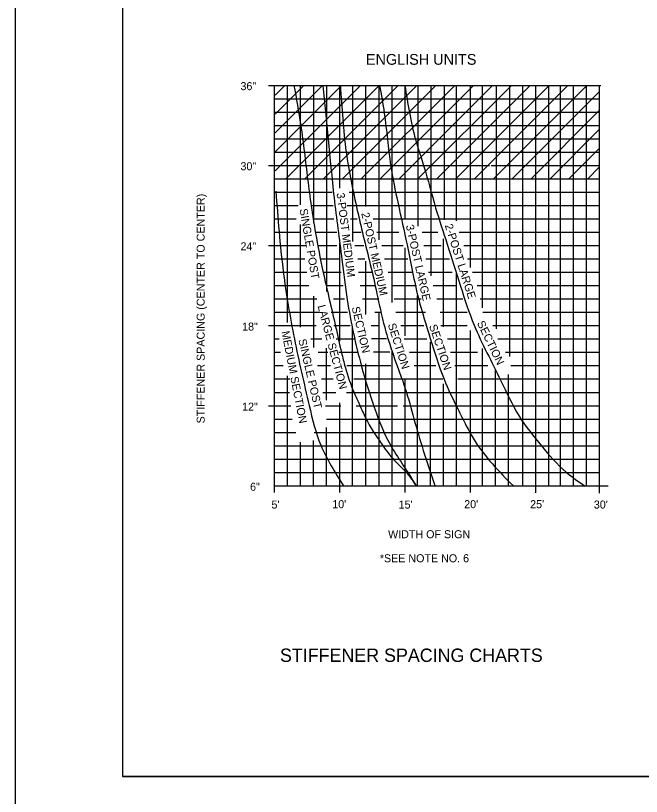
# Model space of a CAD drawing. Extents: x 650495 to 651400, y 297864 to 299646.
# Drawn here: x 650495.3 to 650729.8, y 299059.1 to 299351.6 of the extents above; entities that cross this region are included whole.
import ezdxf

# ---------------------------------------------------------------- set-up
doc = ezdxf.new("R2010")
doc.units = 0
for name, color, linetype in [('1', 7, 'Continuous'), ('2', 7, 'Continuous'), ('3', 7, 'Continuous'), ('PLT-BNDY', 7, 'Continuous')]:
    doc.layers.add(name, color=color, linetype=linetype)

msp = doc.modelspace()

# ---------------------------------------------------------------- linework, layer by layer
at = {"layer": '1'}
for p, q in [((650535.31, 299630.63), (650535.31, 299066.63)), ((651321.31, 299066.63), (650535.31, 299066.63)), ((650535.31, 299066.63), (651121.31, 299066.63))]:
    msp.add_line(p, q, dxfattribs=at)
at = {"layer": '2'}
for p, q in [((650590.03, 299325.48), (650714.65, 299325.48)), ((650592.53, 299321.8), (650596.21, 299325.48)), ((650592.53, 299314.72), (650603.28, 299325.48)), ((650592.53, 299307.65), (650610.36, 299325.48)), ((650592.53, 299300.58), (650617.43, 299325.48)), ((650592.53, 299293.51), (650624.5, 299325.48)), ((650595.28, 299325.48), (650595.28, 299325.48)), ((650596.57, 299290.48), (650631.57, 299325.48)), ((650603.64, 299290.48), (650638.64, 299325.48)), ((650607.53, 299325.48), (650607.53, 299325.48)), ((650610.71, 299290.48), (650645.71, 299325.48)), ((650617.78, 299290.48), (650652.78, 299325.48)), ((650624.85, 299290.48), (650659.85, 299325.48)), ((650625.9, 299325.48), (650625.9, 299325.48)), ((650631.28, 299325.48), (650631.28, 299325.48)), ((650631.92, 299290.48), (650666.92, 299325.48)), ((650639, 299290.48), (650674, 299325.48)), ((650646.07, 299290.48), (650681.07, 299325.48)), ((650653.14, 299290.48), (650688.14, 299325.48)), ((650660.21, 299290.48), (650695.21, 299325.48)), ((650661.15, 299325.48), (650661.15, 299325.48)), ((650667.28, 299290.48), (650702.28, 299325.48)), ((650674.35, 299290.48), (650709.35, 299325.48)), ((650681.42, 299290.48), (650714.03, 299323.09)), ((650592.53, 299320.48), (650714.03, 299320.48)), ((650607.53, 299320.48), (650607.53, 299320.48)), ((650632.53, 299317.86), (650632.53, 299317.86)), ((650688.49, 299290.48), (650714.03, 299316.02)), ((650592.53, 299315.48), (650714.03, 299315.48)), ((650592.53, 299310.48), (650714.03, 299310.48)), ((650633.65, 299310.48), (650633.65, 299310.48)), ((650695.56, 299290.48), (650714.03, 299308.95)), ((650592.53, 299305.48), (650714.03, 299305.48)), ((650627.53, 299305.48), (650627.53, 299305.48)), ((650665.15, 299305.48), (650665.15, 299305.48)), ((650702.63, 299290.48), (650714.03, 299301.87)), ((650592.53, 299300.48), (650714.03, 299300.48)), ((650590.03, 299295.48), (650672.9, 299295.48)), ((650597.53, 299295.48), (650597.53, 299295.48)), ((650636.78, 299295.48), (650636.78, 299295.48)), ((650673.53, 299295.48), (650714.03, 299295.48)), ((650709.71, 299290.48), (650714.03, 299294.8)), ((650592.53, 299290.48), (650714.03, 299290.48)), ((650609.9, 299290.48), (650609.9, 299290.48)), ((650592.53, 299285.48), (650613.94, 299285.48)), ((650620.28, 299285.48), (650714.03, 299285.48)), ((650592.53, 299280.48), (650601.15, 299280.48)), ((650605.9, 299280.48), (650614.33, 299280.48)), ((650619.59, 299280.48), (650714.03, 299280.48)), ((650592.53, 299275.48), (650600.46, 299275.48)), ((650606.9, 299275.48), (650614.53, 299275.48)), ((650612.53, 299275.48), (650612.53, 299275.48)), ((650620.77, 299275.48), (650623.35, 299275.48)), ((650629.3, 299275.48), (650714.03, 299275.48)), ((650592.53, 299270.48), (650601.85, 299270.48)), ((650607.78, 299270.48), (650615.72, 299270.48)), ((650621.67, 299270.48), (650624.74, 299270.48)), ((650630.68, 299270.48), (650638.9, 299270.48)), ((650647.62, 299270.48), (650653.57, 299270.48)), ((650661.5, 299270.48), (650714.03, 299270.48)), ((650590.03, 299265.48), (650604.15, 299265.48)), ((650608.78, 299265.48), (650615.62, 299265.48)), ((650622.36, 299265.48), (650625.73, 299265.48)), ((650632.57, 299265.48), (650640.53, 299265.48)), ((650648.22, 299265.48), (650654.76, 299265.48)), ((650663.28, 299265.48), (650714.03, 299265.48)), ((650592.53, 299260.48), (650603.63, 299260.48)), ((650609.65, 299260.48), (650616.65, 299260.48)), ((650623.55, 299260.48), (650626.22, 299260.48)), ((650633.56, 299260.48), (650642.28, 299260.48)), ((650647.53, 299260.48), (650647.53, 299260.48)), ((650649.01, 299260.48), (650657.93, 299260.48)), ((650664.67, 299260.48), (650714.03, 299260.48)), ((650592.53, 299255.48), (650604.43, 299255.48)), ((650610.65, 299255.48), (650617.31, 299255.48)), ((650623.85, 299255.48), (650628.8, 299255.48)), ((650634.94, 299255.48), (650643.9, 299255.48)), ((650650, 299255.48), (650658.92, 299255.48)), ((650666.45, 299255.48), (650714.03, 299255.48)), ((650592.53, 299250.48), (650605.22, 299250.48)), ((650611.65, 299250.48), (650618.1, 299250.48)), ((650624.44, 299250.48), (650629.99, 299250.48)), ((650636.13, 299250.48), (650645.53, 299250.48)), ((650651.79, 299250.48), (650660.31, 299250.48)), ((650668.23, 299250.48), (650714.03, 299250.48)), ((650592.53, 299245.48), (650608.15, 299245.48)), ((650614.43, 299245.48), (650618.6, 299245.48)), ((650625.23, 299245.48), (650631.38, 299245.48)), ((650637.12, 299245.48), (650647.28, 299245.48)), ((650653.17, 299245.48), (650662.88, 299245.48)), ((650669.42, 299245.48), (650714.03, 299245.48)), ((650592.53, 299240.48), (650609.15, 299240.48)), ((650607.53, 299240.48), (650607.53, 299240.48)), ((650613.53, 299240.48), (650619.69, 299240.48)), ((650629.9, 299240.48), (650632.37, 299240.48)), ((650637.72, 299240.48), (650648.9, 299240.48)), ((650654.36, 299240.48), (650664.47, 299240.48)), ((650670.41, 299240.48), (650714.03, 299240.48)), ((650590.03, 299235.48), (650607.9, 299235.48)), ((650592.53, 299235.48), (650592.53, 299235.48)), ((650614.53, 299235.48), (650620.68, 299235.48)), ((650628.6, 299235.48), (650631.18, 299235.48)), ((650639.7, 299235.48), (650648.22, 299235.48)), ((650648.78, 299235.48), (650648.78, 299235.48)), ((650654.65, 299235.48), (650664.47, 299235.48)), ((650674.18, 299235.48), (650714.03, 299235.48)), ((650592.53, 299230.48), (650594.12, 299230.48)), ((650605.91, 299230.48), (650610.07, 299230.48)), ((650615.4, 299230.48), (650622.36, 299230.48)), ((650634.25, 299230.48), (650628.7, 299230.48)), ((650640.89, 299230.48), (650649.41, 299230.48)), ((650657.14, 299230.48), (650665.85, 299230.48)), ((650675.96, 299230.48), (650714.03, 299230.48)), ((650592.53, 299225.48), (650594.52, 299225.48)), ((650608.69, 299225.48), (650612.28, 299225.48)), ((650616.4, 299225.48), (650623.75, 299225.48)), ((650635.54, 299225.48), (650629.39, 299225.48)), ((650642.87, 299225.48), (650650.6, 299225.48)), ((650658.32, 299225.48), (650668.43, 299225.48)), ((650678.93, 299225.48), (650714.03, 299225.48)), ((650592.53, 299220.48), (650595.51, 299220.48)), ((650608.49, 299220.48), (650613.28, 299220.48)), ((650619.39, 299220.48), (650635.93, 299220.48)), ((650644.65, 299220.48), (650652.78, 299220.48)), ((650659.91, 299220.48), (650672.2, 299220.48)), ((650680.91, 299220.48), (650714.03, 299220.48)), ((650708.9, 299220.48), (650708.9, 299220.48)), ((650592.53, 299215.48), (650598.03, 299215.48)), ((650609.88, 299215.48), (650614.28, 299215.48)), ((650612.53, 299215.48), (650612.53, 299215.48)), ((650622.06, 299215.48), (650655.45, 299215.48)), ((650659.9, 299215.48), (650659.9, 299215.48)), ((650661, 299215.48), (650714.03, 299215.48)), ((650592.53, 299210.48), (650597.99, 299210.48)), ((650610.47, 299210.48), (650615.28, 299210.48)), ((650619.28, 299210.48), (650714.03, 299210.48)), ((650590.03, 299205.48), (650598.48, 299205.48)), ((650597.53, 299205.48), (650597.53, 299205.48)), ((650611.46, 299205.48), (650617.21, 299205.48)), ((650622.95, 299205.48), (650638.4, 299205.48)), ((650640.53, 299205.48), (650714.03, 299205.48)), ((650592.53, 299200.48), (650598.98, 299200.48)), ((650611.86, 299200.48), (650714.03, 299200.48)), ((650592.53, 299195.48), (650600.27, 299195.48)), ((650607.15, 299195.48), (650714.03, 299195.48)), ((650642.53, 299195.48), (650642.53, 299195.48)), ((650686.78, 299195.48), (650686.78, 299195.48)), ((650592.53, 299190.48), (650714.03, 299190.48)), ((650692.53, 299190.48), (650692.53, 299190.48)), ((650592.53, 299185.48), (650714.03, 299185.48)), ((650627.53, 299185.48), (650627.53, 299185.48)), ((650650.15, 299185.48), (650650.15, 299185.48)), ((650687.53, 299185.48), (650687.53, 299185.48)), ((650699.9, 299185.48), (650699.9, 299185.48)), ((650592.53, 299180.48), (650714.03, 299180.48)), ((650607.53, 299180.48), (650607.53, 299180.48)), ((650592.15, 299175.48), (650717.28, 299175.48)), ((650712.53, 299175.48), (650712.53, 299175.48))]:
    msp.add_line(p, q, dxfattribs=at)
for points in [[(650592.15, 299325.48), (650592.15, 299172.98)], [(650597.03, 299325.48), (650597.03, 299236.61)], [(650601.9, 299325.48), (650601.9, 299280.74)], [(650606.9, 299325.48), (650606.9, 299273.98)], [(650611.78, 299325.48), (650611.78, 299248.23)], [(650616.65, 299325.48), (650616.65, 299286.98)], [(650621.53, 299325.48), (650621.53, 299266.96)], [(650626.4, 299325.48), (650626.4, 299280.04)], [(650631.4, 299325.48), (650631.4, 299267.56)], [(650636.28, 299325.48), (650636.28, 299244.17)], [(650641.15, 299325.48), (650641.15, 299275.36)], [(650646.03, 299325.48), (650646.03, 299272.71)], [(650650.9, 299325.48), (650650.9, 299254.08)], [(650655.9, 299325.48), (650655.9, 299275.09)], [(650660.4, 299325.48), (650660.4, 299274.69)], [(650665.65, 299325.48), (650665.65, 299257.25)], [(650670.15, 299325.48), (650670.15, 299242.19)], [(650675.4, 299325.48), (650675.4, 299234.26)], [(650680.4, 299325.48), (650680.4, 299223.95)], [(650685.28, 299325.48), (650685.28, 299175.48)], [(650690.15, 299325.48), (650690.15, 299172.81)], [(650695.03, 299325.48), (650695.03, 299175.48)], [(650699.4, 299325.48), (650699.4, 299175.48)], [(650704.28, 299325.48), (650704.28, 299175.48)], [(650709.15, 299325.48), (650709.15, 299175.48)], [(650714.03, 299325.48), (650714.03, 299172.77)], [(650601.9, 299273.4), (650601.9, 299234.86)], [(650616.65, 299266.47), (650616.65, 299229.6)], [(650655.53, 299267.95), (650655.53, 299235.05)], [(650641.15, 299264.61), (650641.15, 299231.68)], [(650626.4, 299259.63), (650626.4, 299239.61)], [(650660.4, 299255.47), (650660.4, 299175.48)], [(650606.9, 299246.45), (650606.9, 299227.22)], [(650645.78, 299246.75), (650645.78, 299175.48)], [(650631.4, 299240.6), (650631.4, 299175.48)], [(650621.4, 299235.05), (650621.4, 299175.48)], [(650665.65, 299233.66), (650665.65, 299172.98)], [(650650.65, 299229.3), (650650.65, 299175.48)], [(650611.65, 299226.98), (650611.65, 299207.6)], [(650636.28, 299225.93), (650636.28, 299175.48)], [(650670.15, 299226.93), (650670.15, 299175.48)], [(650626.4, 299221.18), (650626.4, 299175.48)], [(650597.03, 299216.72), (650597.03, 299175.48)], [(650675.03, 299219), (650675.03, 299175.48)], [(650679.9, 299217.21), (650679.9, 299175.48)], [(650641.15, 299215.63), (650641.15, 299172.98)], [(650655.53, 299213.65), (650655.53, 299175.48)], [(650616.65, 299206.61), (650616.65, 299172.98)], [(650611.65, 299197.29), (650611.65, 299175.48)], [(650601.9, 299191.84), (650601.9, 299175.48)], [(650606.78, 299192.44), (650606.78, 299175.48)]]:
    msp.add_lwpolyline(points, dxfattribs=at)
for points in [[(650599.57, 299325.48), (650602.15, 299310.57), (650604.72, 299290.35), (650607.7, 299270.13), (650610.47, 299255.86), (650612.85, 299245.36), (650615.23, 299235.05), (650617.41, 299225.34), (650618.79, 299219.99), (650622.16, 299210.28), (650624.14, 299205.92), (650626.52, 299200.76), (650629.3, 299195.81), (650632.27, 299191.45), (650636.63, 299185.7), (650641.98, 299180.15), (650645.35, 299175.48)], [(650610.47, 299325.48), (650612.45, 299305.41), (650614.63, 299283.41), (650617.6, 299260.22), (650619.59, 299245.16), (650624.94, 299220.19), (650629.69, 299204.93), (650636.23, 299189.86), (650640.59, 299183.12), (650645.35, 299175.48)], [(650617.01, 299325.48), (650619.19, 299300.48), (650623.35, 299278.66), (650624.94, 299271.72), (650630.09, 299250.31), (650632.66, 299238.52), (650635.04, 299229.9), (650638.81, 299219), (650641.78, 299210.48), (650644.95, 299199.18), (650652.48, 299175.2)], [(650631.67, 299325.48), (650633.46, 299315.12), (650635.83, 299295.5), (650638.61, 299281.23), (650641.98, 299265.77), (650646.34, 299245.36), (650650.7, 299230.69), (650655.85, 299215.43), (650661, 299204.33), (650664.17, 299197.99), (650667.14, 299192.64), (650681.81, 299175.48)], [(650641.18, 299325.48), (650645.15, 299305.22), (650648.32, 299295.11), (650652.68, 299279.65), (650657.04, 299265.97), (650661.99, 299250.31), (650667.14, 299235.65), (650677.05, 299215.03), (650683.99, 299201.56), (650692.31, 299190.46), (650701.62, 299180.55), (650708.75, 299175.39)], [(650592.84, 299285.79), (650595.61, 299255.66), (650599.77, 299230.49), (650605.32, 299205.52), (650609.68, 299190.66), (650618.2, 299175.48)]]:
    msp.add_spline(points, degree=3, dxfattribs=at)
at = {"layer": 'PLT-BNDY'}
msp.add_lwpolyline([(650495.31, 299645.63), (651336.31, 299645.63), (651336.31, 299051.63), (650495.31, 299051.63)], close=True, dxfattribs=at)

# ---------------------------------------------------------------- texts
at = {"layer": '2'}
for s, height, p in [('ENGLISH UNITS', 4.0375, (650626.58, 299333.19)), ('WIDTH OF SIGN', 3, (650634.88, 299155.83)), ('*SEE NOTE NO. 6', 3, (650631.78, 299146.83)), ('STIFFENER SPACING CHARTS', 5, (650594.37, 299109.5))]:
    msp.add_text(s, height=height, dxfattribs=at).set_placement(p)
for s, height, rotation, p in [('STIFFENER SPACING (CENTER TO CENTER)', 3, 90, (650566.15, 299198.84)), ('3-POST MEDIUM', 2.9992, 277.2906, (650615.57, 299285.05)), ('SINGLE POST', 3, 279.7906, (650601.68, 299279.06)), ('2-POST MEDIUM', 3, 282.7906, (650624.81, 299277.53)), ('3-POST LARGE', 3, 282.7906, (650641.5, 299272.94)), ('2-POST LARGE', 3, 287.7906, (650656.08, 299273.04)), ('LARGE SECTION', 3, 284.7906, (650608.43, 299242.83)), ('SECTION', 2.999, 283.2906, (650621.22, 299242.27)), ('SECTION', 3, 295.7906, (650668.11, 299236.44)), ('SECTION', 3, 287.7906, (650634.73, 299235.86)), ('SECTION', 3, 288.7906, (650650.18, 299235.37)), ('MEDIUM SECTION', 3, 281.0612, (650594.91, 299233.18)), ('SINGLE POST', 3, 283.0612, (650601.24, 299230.16))]:
    msp.add_text(s, height=height, rotation=rotation, dxfattribs=at).set_placement(p)
at = {"layer": '3'}
for s, p in [('36"', (650579.57, 299323.68)), ('30"', (650579.57, 299293.68)), ('24"', (650579.57, 299263.68)), ('18"', (650580.18, 299233.61)), ('12"', (650580.18, 299203.61)), ('6"', (650583.16, 299173.61)), ("5'", (650591.18, 299166.95)), ("10'", (650613.97, 299167.09)), ("15'", (650638.83, 299166.95)), ("20'", (650663.4, 299167.09)), ("25'", (650688.11, 299167.09)), ("30'", (650711.97, 299166.95))]:
    msp.add_text(s, height=3, dxfattribs=at).set_placement(p)

doc.saveas('drawing.dxf')
